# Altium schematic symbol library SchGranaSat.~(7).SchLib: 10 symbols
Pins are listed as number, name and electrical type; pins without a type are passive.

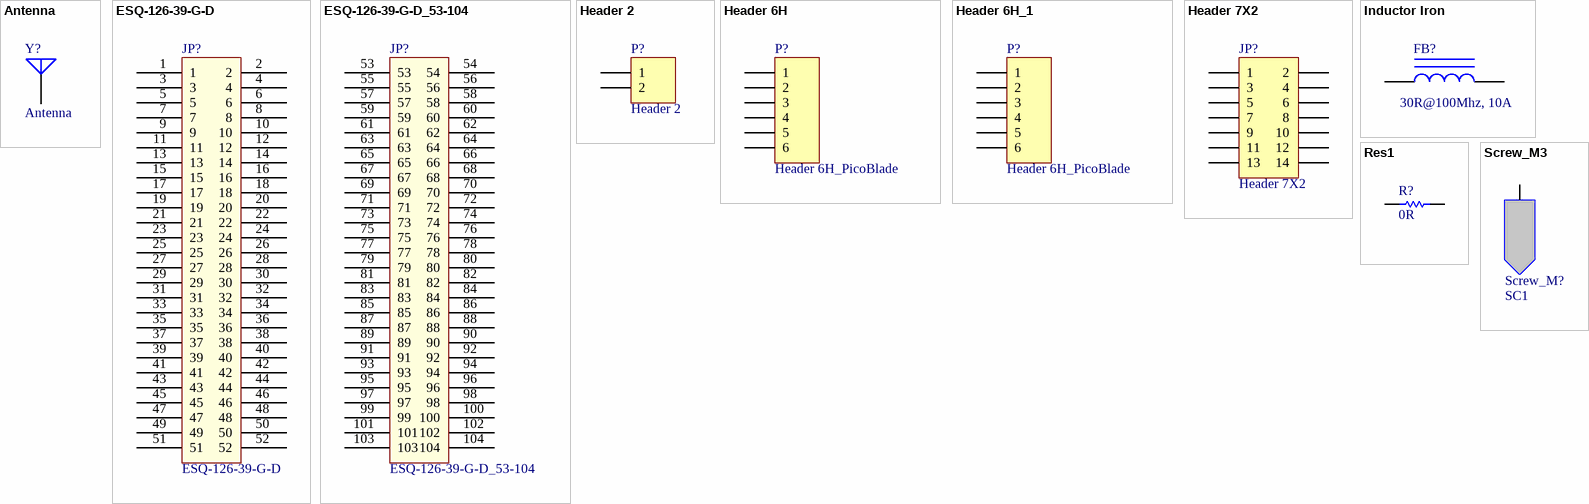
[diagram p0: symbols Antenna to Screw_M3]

## Antenna
designator Y?
Generic Antenna
footprint PIN1 (Generic Antenna; 1 Lead)
pins: 1 A

## ESQ-126-39-G-D
designator JP?
Cubesat Header Connector; Shop: es.rs-online.com; Localización: Último cajón cajonera blanca entre Pablo y Luis; Reference: 254-6132
footprint ESQ-126-39-G-D (Cubesat Connector; Header; 26x2 Position)
pins: 1, 2, 3, 4, 5, 6, 7, 8, 9, 10, 11, 12, 13, 14, 15, 16, 17, 18, 19, 20, 21, 22, 23, 24, 25, 26, 27, 28, 29, 30, 31, 32, 33, 34, 35, 36, 37, 38, 39, 40, 41, 42, 43, 44, 45, 46, 47, 48, 49, 50, 51, 52

## ESQ-126-39-G-D_53-104
designator JP?
Cubesat Header Connector; Shop: es.rs-online.com; Localización: Último cajón cajonera blanca entre Pablo y Luis; Reference: 254-6132
footprint ESQ-126-39-G-D_53_104 (Cubesat Connector; Header; 26x2 Position)
pins: 53, 54, 55, 56, 57, 58, 59, 60, 61, 62, 63, 64, 65, 66, 67, 68, 69, 70, 71, 72, 73, 74, 75, 76, 77, 78, 79, 80, 81, 82, 83, 84, 85, 86, 87, 88, 89, 90, 91, 92, 93, 94, 95, 96, 97, 98, 99, 100, 101, 102, 103, 104

## Header 2
designator P?
Header, 2-Pin
footprint HDR1X2 (Connector; Header; 2 Position)
signal-integrity model Connector
pins: 1, 2

## Header 6H
designator P?, comment Header 6H_PicoBlade
Header, 6-Pin, Left Angle
footprint HDR1X6H (Connector; Header; 6 Position; Right Angle)
signal-integrity model Connector
pins: 1, 2, 3, 4, 5, 6

## Header 6H_1
designator P?, comment Header 6H_PicoBlade
Header, 6-Pin, Right Angle
signal-integrity model Connector
footprint HDR1X6H (Connector; Header; 6 Position; Right Angle)
pins: 1, 2, 3, 4, 5, 6

## Header 7X2
designator JP?
Header, 7-Pin, Dual row
footprint HDR2X7 (Connector; Header; 7x2 Position)
signal-integrity model Connector
pins: 1, 2, 3, 4, 5, 6, 7, 8, 9, 10, 11, 12, 13, 14

## Inductor Iron
designator FB?  value 30R@100Mhz, 10A
Magnetic-Core Inductor
simulation model INDUCTOR (Inductor)
signal-integrity model Inductor Iron
footprint INDC3216 (Chip Inductor, Body 3.2x1.6mm, IPC High Density)
pins: 1, 2

## Res1
designator R?, comment 0R
Resistor
simulation model RESISTOR (Resistor)
signal-integrity model Res
footprint R
pins: 1, 2

## Screw_M3
designator Screw_M?, comment SC1
Main CubeSAT bus
footprint Screw_M3 (Main CubeSAT bus M3 screw)
pins: 1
